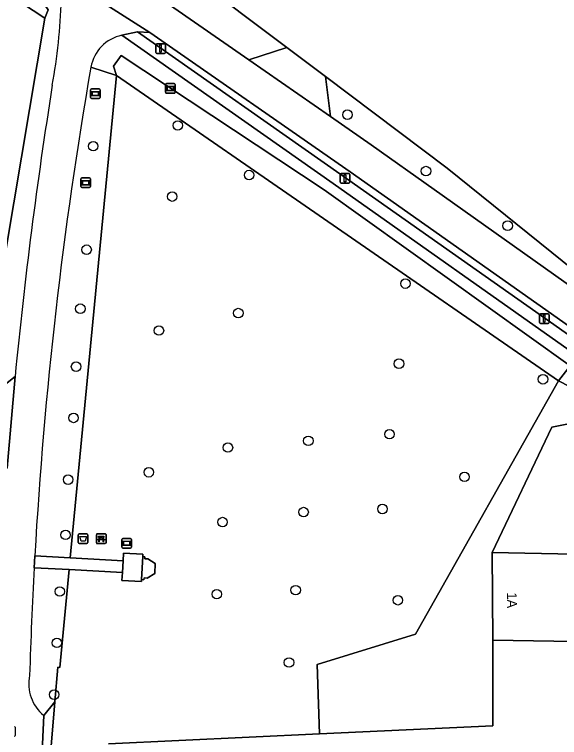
# Model space of a CAD drawing. Extents: x 163859 to 164644, y 379566 to 382155.
# Drawn here: x 164442.4 to 164498.5, y 381606.4 to 381680.8 of the extents above; entities that cross this region are included whole.
import ezdxf

# ---------------------------------------------------------------- set-up
doc = ezdxf.new("R2010")
doc.units = 0
for name, color, linetype in [('IMGEO_Afvalbak', 7, 'Continuous'), ('IMGEO_Bank', 7, 'Continuous'), ('IMGEO_Boom', 7, 'Continuous'), ('IMGEO_Erf', 7, 'Continuous'), ('IMGEO_Groenvoorziening', 7, 'Continuous'), ('IMGEO_Haag', 7, 'Continuous'), ('IMGEO_Hek', 7, 'Continuous'), ('IMGEO_Informatiebord', 7, 'Continuous'), ('IMGEO_Lichtmast', 7, 'Continuous'), ('IMGEO_Loofbos', 7, 'Continuous'), ('IMGEO_Pand', 7, 'Continuous'), ('IMGEO_Pand_nummerreeks', 7, 'Continuous'), ('IMGEO_Rijbaan_lokaal_gesloten', 7, 'Continuous'), ('IMGEO_Rioolput', 7, 'Continuous'), ('IMGEO_Verklikker', 7, 'Continuous'), ('IMGEO_Voetpad_open', 7, 'Continuous'), ('IMGEO_Waterloop', 7, 'Continuous'), ('IMGEO_Wegwijzer', 7, 'Continuous')]:
    doc.layers.add(name, color=color, linetype=linetype)

msp = doc.modelspace()

# ---------------------------------------------------------------- linework, layer by layer
at = {"layer": 'IMGEO_Afvalbak'}
for p, q in [((164448.954, 381626.452), (164448.954, 381627.252)), ((164448.954, 381627.252), (164448.954, 381626.452)), ((164449.054, 381627.352), (164449.844, 381627.352)), ((164449.844, 381627.352), (164449.054, 381627.352)), ((164449.944, 381627.252), (164449.944, 381626.452)), ((164449.944, 381626.452), (164449.944, 381627.252)), ((164449.844, 381626.352), (164449.054, 381626.352)), ((164449.054, 381626.352), (164449.844, 381626.352))]:
    msp.add_line(p, q, dxfattribs=at)
msp.add_lwpolyline([(164449.097, 381627.066), (164449.801, 381627.066), (164449.652, 381626.596), (164449.246, 381626.596), (164449.097, 381627.066)], dxfattribs=at)
for centre, start, end in [((164449.054, 381627.252), 90, 180), ((164449.054, 381627.252), 90, 180), ((164449.844, 381627.252), 0, 90), ((164449.844, 381627.252), 360, 90), ((164449.054, 381626.452), 180, 270), ((164449.054, 381626.452), 180, 270), ((164449.844, 381626.452), 270, 0), ((164449.844, 381626.452), 270, 0)]:
    msp.add_arc(centre, 0.1, start, end, dxfattribs=at)
at = {"layer": 'IMGEO_Bank'}
for p, q in [((164450.809, 381626.422), (164450.809, 381627.263)), ((164450.809, 381627.263), (164450.809, 381626.422)), ((164450.884, 381627.347), (164451.725, 381627.347)), ((164451.725, 381627.347), (164450.884, 381627.347)), ((164451.118, 381626.853), (164451.118, 381626.959)), ((164451.162, 381626.959), (164451.162, 381626.853)), ((164451.45, 381626.965), (164451.168, 381626.965)), ((164451.168, 381626.847), (164451.45, 381626.847)), ((164451.456, 381626.853), (164451.456, 381626.959)), ((164451.5, 381626.959), (164451.5, 381626.853)), ((164451.809, 381627.272), (164451.809, 381626.431)), ((164451.809, 381626.431), (164451.809, 381627.272)), ((164451.734, 381626.347), (164450.893, 381626.347)), ((164450.893, 381626.347), (164451.734, 381626.347)), ((164451.506, 381626.745), (164451.113, 381626.745))]:
    msp.add_line(p, q, dxfattribs=at)
for points in [[(164451.056, 381626.745), (164450.914, 381626.745), (164451.026, 381626.847), (164451.112, 381626.847)], [(164451.112, 381626.965), (164451.026, 381626.965), (164451.026, 381627.126), (164451.589, 381627.126), (164451.589, 381626.965), (164451.506, 381626.965)], [(164451.506, 381626.847), (164451.589, 381626.847), (164451.701, 381626.745), (164451.562, 381626.745)], [(164451.106, 381626.738), (164451.106, 381626.531), (164451.063, 381626.531), (164451.063, 381626.738)], [(164451.556, 381626.738), (164451.556, 381626.531), (164451.512, 381626.531), (164451.512, 381626.738)]]:
    msp.add_lwpolyline(points, dxfattribs=at)
for centre, radius, start, end in [((164450.887, 381627.269), 0.0779, 92.4484, 184.28452), ((164450.887, 381627.269), 0.0779, 92.4484, 184.28452), ((164451.111, 381626.958), 0.00671, 2.89567, 87.10433), ((164451.111, 381626.854), 0.00671, 272.89567, 357.10433), ((164451.168, 381626.958), 0.00671, 92.89567, 177.10433), ((164451.168, 381626.854), 0.00671, 182.89567, 267.10433), ((164451.45, 381626.958), 0.00671, 2.89567, 87.10433), ((164451.45, 381626.854), 0.00671, 272.89567, 357.10433), ((164451.507, 381626.958), 0.00671, 92.89567, 177.10433), ((164451.507, 381626.854), 0.00671, 182.89567, 267.10433), ((164451.731, 381627.269), 0.0779, 2.4484, 94.28452), ((164451.731, 381627.269), 0.0779, 2.4484, 94.28452), ((164450.887, 381626.425), 0.0779, 182.4484, 274.28452), ((164450.887, 381626.425), 0.0779, 182.4484, 274.28452), ((164451.056, 381626.738), 0.00671, 2.89567, 87.10433), ((164451.113, 381626.738), 0.00671, 92.89567, 177.10433), ((164451.505, 381626.738), 0.00671, 2.89567, 87.10433), ((164451.562, 381626.738), 0.00671, 92.89567, 177.10433), ((164451.731, 381626.425), 0.0779, 272.4484, 4.28452), ((164451.731, 381626.425), 0.0779, 272.4484, 4.28452)]:
    msp.add_arc(centre, radius, start, end, dxfattribs=at)
at = {"layer": 'IMGEO_Boom'}
for centre in [(164476.665, 381670.499), (164459.197, 381669.393), (164450.485, 381667.25), (164466.538, 381664.286), (164484.752, 381664.694), (164458.621, 381662.067), (164493.161, 381659.073), (164449.805, 381656.599), (164482.639, 381653.106), (164449.161, 381650.525), (164465.427, 381650.075), (164457.255, 381648.275), (164448.719, 381644.56), (164481.97, 381644.867), (164496.797, 381643.258), (164448.464, 381639.282), (164480.993, 381637.606), (164472.636, 381636.923), (164464.36, 381636.23), (164456.212, 381633.684), (164488.717, 381633.215), (164447.903, 381632.926), (164472.149, 381629.589), (164480.27, 381629.907), (164463.805, 381628.56), (164447.636, 381627.239), (164447.045, 381621.415), (164463.212, 381621.138), (164471.332, 381621.555), (164481.856, 381620.51), (164446.75, 381616.126), (164470.647, 381614.104), (164446.459, 381610.795)]:
    msp.add_circle(centre, 0.489, dxfattribs=at)
at = {"layer": 'IMGEO_Erf'}
for points in [[(164460.508, 381684.892), (164470.413, 381677.426), (164474.397, 381674.423), (164486.922, 381664.983), (164500, 381654.462), (164509.162, 381647.672), (164516.979, 381640.96), (164517.33, 381641.342), (164526.033, 381633.218), (164529.147, 381634.828), (164538.792, 381645.898), (164541.993, 381649.77), (164537.255, 381661.598), (164540.318, 381662.825), (164543.407, 381655.115), (164544.635, 381652.966), (164545.262, 381652.467), (164553.793, 381662.786), (164565.496, 381676.942), (164583.03, 381701.542)], [(164504.238, 381639.639), (164497.717, 381638.341), (164491.561, 381625.418), (164500, 381625.257), (164511.742, 381625.032), (164511.845, 381616.048), (164500, 381616.257), (164491.641, 381616.405), (164491.641, 381607.592), (164473.792, 381606.759), (164452.065, 381605.746)]]:
    msp.add_lwpolyline(points, dxfattribs=at)
at = {"layer": 'IMGEO_Groenvoorziening'}
for points in [[(164455.903, 381683.819), (164455.774, 381683.629), (164466.526, 381676.141), (164470.413, 381677.426), (164460.508, 381684.892), (164456.242, 381696.233), (164452.839, 381705.104), (164451.098, 381709.418), (164447.311, 381716.527), (164449.308, 381717.487), (164446.861, 381722.173), (164445.218, 381721.442), (164440.48, 381732.584), (164442.117, 381733.052), (164440.833, 381734.263), (164434.331, 381751.745), (164433.997, 381752.734), (164433.526, 381754.803), (164427.546, 381772.442), (164427.349, 381773.022), (164418.253, 381799.855)], [(164413.488, 381705.549), (164411.502, 381706.899), (164410.178, 381704.987), (164411.398, 381704.132), (164412.893, 381702.27), (164413.634, 381703.357), (164430.229, 381692.16), (164429.462, 381691.018), (164430.172, 381690.536), (164431.154, 381689.854), (164431.926, 381691.02), (164445.149, 381682.312), (164445.862, 381681.301), (164445.507, 381680.437), (164441.513, 381656.721), (164439.427, 381648.452), (164432.979, 381644.03), (164435.396, 381638.772), (164437.55, 381639.663), (164442.442, 381643.541)], [(164501.109, 381647.553), (164500, 381648.336), (164476.958, 381664.61), (164456.317, 381678.951), (164455.059, 381679.039), (164475.88, 381664.403), (164500, 381647.421), (164500.789, 381646.866)], [(164500.075, 381645.858), (164475.205, 381663.4), (164453.434, 381678.671)], [(164450.243, 381675.391), (164452.879, 381674.516), (164452.567, 381675.49), (164453.363, 381676.591), (164474.271, 381662.773), (164499.591, 381644.652), (164498.403, 381643.097), (164501.803, 381641.347), (164502.858, 381642.512)], [(164444.471, 381625.076), (164448.124, 381624.873), (164452.879, 381674.516), (164450.243, 381675.391)], [(164498.403, 381643.097), (164452.879, 381674.516), (164448.124, 381624.873), (164453.557, 381624.572), (164453.606, 381625.363), (164455.592, 381625.266), (164455.587, 381625.002), (164455.795, 381624.993), (164455.786, 381624.774), (164456.113, 381624.78), (164456.861, 381624.28), (164456.823, 381623.267), (164456.038, 381622.8), (164455.723, 381622.822), (164455.709, 381622.622), (164455.463, 381622.639), (164455.452, 381622.46), (164453.447, 381622.561), (164453.504, 381623.384), (164448.008, 381623.666), (164447.044, 381613.598), (164446.845, 381613.615), (164446.54, 381610.042), (164445.729, 381600.527)], [(164500, 381654.462), (164486.922, 381664.983), (164474.397, 381674.423), (164474.908, 381670.303), (164479.098, 381667.385), (164485.583, 381662.794), (164500, 381652.587), (164503.048, 381650.429)], [(164452.065, 381605.746), (164473.792, 381606.759), (164473.688, 381609.802), (164473.548, 381613.906), (164483.66, 381617.038), (164498.403, 381643.097)], [(164446.039, 381571.665), (164445.919, 381582.439), (164445.846, 381586.661), (164445.965, 381592.66), (164445.764, 381596.44), (164445.787, 381598.852), (164445.729, 381600.527), (164446.54, 381610.042), (164445.386, 381608.654), (164445.211, 381604.21)]]:
    msp.add_lwpolyline(points, dxfattribs=at)
msp.add_lwpolyline([(164445.507, 381680.437), (164431.154, 381689.854), (164430.172, 381690.536), (164418.395, 381675.757), (164432.979, 381644.03), (164439.427, 381648.452), (164441.513, 381656.721)], close=True, dxfattribs=at)
for centre, radius, start, end in [((164384.013, 381684.587), 63.236, 349.92525, 357.95994), ((164454.269, 381674.666), 4.091, 101.77804, 169.79792), ((164886.517, 381599.854), 442.765, 170.17716, 176.73442), ((164930.61, 381596.389), 490.439, 170.95102, 174.48297)]:
    msp.add_arc(centre, radius, start, end, dxfattribs=at)
at = {"layer": 'IMGEO_Haag'}
msp.add_lwpolyline([(164501.109, 381647.553), (164500, 381648.336), (164476.958, 381664.61), (164456.317, 381678.951), (164455.059, 381679.039), (164475.88, 381664.403), (164500, 381647.421), (164500.789, 381646.866)], dxfattribs=at)
at = {"layer": 'IMGEO_Hek'}
msp.add_lwpolyline([(164445.507, 381680.437), (164441.513, 381656.721), (164439.427, 381648.452), (164432.979, 381644.03)], dxfattribs=at)
at = {"layer": 'IMGEO_Informatiebord'}
for p, q in [((164453.544, 381626.877), (164454.334, 381626.877)), ((164454.334, 381626.877), (164453.544, 381626.877)), ((164453.444, 381625.977), (164453.444, 381626.777)), ((164453.444, 381626.777), (164453.444, 381625.977)), ((164454.434, 381626.777), (164454.434, 381625.977)), ((164454.434, 381625.977), (164454.434, 381626.777)), ((164454.334, 381625.877), (164453.544, 381625.877)), ((164453.544, 381625.877), (164454.334, 381625.877))]:
    msp.add_line(p, q, dxfattribs=at)
for points in [[(164453.545, 381626.609), (164454.333, 381626.609), (164454.333, 381626.145), (164453.545, 381626.145), (164453.545, 381626.609)], [(164453.61, 381626.544), (164453.61, 381626.21), (164454.268, 381626.21), (164454.268, 381626.544), (164453.61, 381626.544)]]:
    msp.add_lwpolyline(points, dxfattribs=at)
for centre, start, end in [((164453.544, 381626.777), 90, 180), ((164453.544, 381626.777), 90, 180), ((164454.334, 381626.777), 0, 90), ((164454.334, 381626.777), 360, 90), ((164453.544, 381625.977), 180, 270), ((164453.544, 381625.977), 180, 270), ((164454.334, 381625.977), 270, 0), ((164454.334, 381625.977), 270, 0)]:
    msp.add_arc(centre, 0.1, start, end, dxfattribs=at)
at = {"layer": 'IMGEO_Lichtmast'}
for p, q in [((164456.927, 381676.897), (164456.927, 381677.697)), ((164456.927, 381677.697), (164456.927, 381676.897)), ((164457.027, 381677.797), (164457.817, 381677.797)), ((164457.817, 381677.797), (164457.027, 381677.797)), ((164457.917, 381677.697), (164457.917, 381676.897)), ((164457.917, 381676.897), (164457.917, 381677.697)), ((164457.817, 381676.797), (164457.027, 381676.797)), ((164457.027, 381676.797), (164457.817, 381676.797)), ((164475.915, 381663.546), (164475.915, 381664.346)), ((164475.915, 381664.346), (164475.915, 381663.546)), ((164476.015, 381664.446), (164476.805, 381664.446)), ((164476.805, 381664.446), (164476.015, 381664.446)), ((164476.905, 381664.346), (164476.905, 381663.546)), ((164476.905, 381663.546), (164476.905, 381664.346)), ((164476.805, 381663.446), (164476.015, 381663.446)), ((164476.015, 381663.446), (164476.805, 381663.446)), ((164496.432, 381649.104), (164496.432, 381649.904)), ((164496.432, 381649.904), (164496.432, 381649.104)), ((164496.532, 381650.004), (164497.322, 381650.004)), ((164497.322, 381650.004), (164496.532, 381650.004)), ((164497.422, 381649.904), (164497.422, 381649.104)), ((164497.422, 381649.104), (164497.422, 381649.904)), ((164497.322, 381649.004), (164496.532, 381649.004)), ((164496.532, 381649.004), (164497.322, 381649.004))]:
    msp.add_line(p, q, dxfattribs=at)
for points in [[(164457.347, 381677.672), (164457.497, 381677.672), (164457.497, 381676.922), (164457.347, 381676.922), (164457.347, 381677.672)], [(164476.335, 381664.321), (164476.485, 381664.321), (164476.485, 381663.571), (164476.335, 381663.571), (164476.335, 381664.321)], [(164496.852, 381649.879), (164497.002, 381649.879), (164497.002, 381649.129), (164496.852, 381649.129), (164496.852, 381649.879)]]:
    msp.add_lwpolyline(points, dxfattribs=at)
for centre, start, end in [((164457.027, 381677.697), 90, 180), ((164457.027, 381677.697), 90, 180), ((164457.817, 381677.697), 0, 90), ((164457.817, 381677.697), 360, 90), ((164457.027, 381676.897), 180, 270), ((164457.027, 381676.897), 180, 270), ((164457.817, 381676.897), 270, 0), ((164457.817, 381676.897), 270, 0), ((164476.015, 381664.346), 90, 180), ((164476.015, 381664.346), 90, 180), ((164476.805, 381664.346), 0, 90), ((164476.805, 381664.346), 360, 90), ((164476.015, 381663.546), 180, 270), ((164476.015, 381663.546), 180, 270), ((164476.805, 381663.546), 270, 0), ((164476.805, 381663.546), 270, 0), ((164496.532, 381649.904), 90, 180), ((164496.532, 381649.904), 90, 180), ((164497.322, 381649.904), 0, 90), ((164497.322, 381649.904), 360, 90), ((164496.532, 381649.104), 180, 270), ((164496.532, 381649.104), 180, 270), ((164497.322, 381649.104), 270, 0), ((164497.322, 381649.104), 270, 0)]:
    msp.add_arc(centre, 0.1, start, end, dxfattribs=at)
at = {"layer": 'IMGEO_Loofbos'}
for points in [[(164501.803, 381641.347), (164498.403, 381643.097), (164483.66, 381617.038), (164473.548, 381613.906), (164473.688, 381609.802), (164473.792, 381606.759), (164491.641, 381607.592), (164491.641, 381616.405), (164491.561, 381625.418), (164497.717, 381638.341), (164504.238, 381639.639)], [(164445.386, 381608.654), (164446.54, 381610.042), (164446.845, 381613.615), (164447.044, 381613.598), (164448.008, 381623.666), (164444.402, 381623.851)]]:
    msp.add_lwpolyline(points, dxfattribs=at)
for centre, radius, start, end in [((164883.319, 381600.007), 439.564, 176.89047, 178.33678), ((164448.063, 381611.906), 4.212, 168.22638, 230.53116)]:
    msp.add_arc(centre, radius, start, end, dxfattribs=at)
at = {"layer": 'IMGEO_Pand'}
for points in [[(164511.742, 381625.032), (164500, 381625.257), (164491.561, 381625.418), (164491.641, 381616.405), (164500, 381616.257), (164511.845, 381616.048)], [(164455.463, 381622.639), (164455.709, 381622.622), (164455.723, 381622.822), (164456.038, 381622.8), (164456.823, 381623.267), (164456.861, 381624.28), (164456.113, 381624.78), (164455.786, 381624.774), (164455.795, 381624.993), (164455.587, 381625.002)]]:
    msp.add_lwpolyline(points, close=True, dxfattribs=at)
at = {"layer": 'IMGEO_Rijbaan_lokaal_gesloten'}
for points in [[(164503.048, 381650.429), (164500, 381652.587), (164485.583, 381662.794), (164479.098, 381667.385), (164474.908, 381670.303), (164466.526, 381676.141), (164455.774, 381683.629), (164441.191, 381693.787), (164424.684, 381705.234)], [(164424.306, 381700.566), (164445.106, 381686.132), (164456.317, 381678.951), (164476.958, 381664.61), (164500, 381648.336), (164501.109, 381647.553)], [(164453.434, 381678.671), (164455.059, 381679.039), (164456.317, 381678.951), (164445.106, 381686.132), (164446.689, 381684.251), (164446.953, 381683.86)], [(164442.442, 381643.541), (164441.623, 381634.125)], [(164444.402, 381623.851), (164444.436, 381624.464), (164444.471, 381625.076)], [(164445.211, 381604.21), (164445.386, 381608.654)]]:
    msp.add_lwpolyline(points, dxfattribs=at)
for centre, radius, start, end in [((164384.013, 381684.587), 63.236, 349.92525, 357.95994), ((164454.269, 381674.666), 4.091, 101.77804, 169.79792), ((164886.517, 381599.854), 442.765, 170.17716, 176.73442), ((164930.61, 381596.389), 490.439, 170.95102, 174.48297), ((164883.319, 381600.007), 439.564, 176.89047, 178.33678), ((164448.063, 381611.906), 4.212, 168.22638, 230.53116)]:
    msp.add_arc(centre, radius, start, end, dxfattribs=at)
at = {"layer": 'IMGEO_Rioolput'}
msp.add_line((164442.451, 381607.432), (164442.451, 381606.58), dxfattribs=at)
msp.add_lwpolyline([(164442.451, 381607.432), (164442.451, 381606.58)], dxfattribs=at)
for centre, start, end in [((164442.375, 381607.43), 1.55205, 88.44795), ((164442.375, 381607.43), 1.55205, 88.44795), ((164442.375, 381606.582), 271.55205, 358.44795), ((164442.375, 381606.582), 271.55205, 358.44795)]:
    msp.add_arc(centre, 0.0765, start, end, dxfattribs=at)
at = {"layer": 'IMGEO_Verklikker'}
for p, q in [((164458.043, 381673.701), (164458.833, 381673.701)), ((164458.833, 381673.701), (164458.043, 381673.701)), ((164457.943, 381672.801), (164457.943, 381673.601)), ((164457.943, 381673.601), (164457.943, 381672.801)), ((164458.933, 381673.601), (164458.933, 381672.801)), ((164458.933, 381672.801), (164458.933, 381673.601)), ((164458.833, 381672.701), (164458.043, 381672.701)), ((164458.043, 381672.701), (164458.833, 381672.701))]:
    msp.add_line(p, q, dxfattribs=at)
for points in [[(164458.044, 381673.433), (164458.832, 381673.433), (164458.832, 381672.969), (164458.044, 381672.969), (164458.044, 381673.433)], [(164458.109, 381673.368), (164458.109, 381673.034), (164458.767, 381673.034), (164458.767, 381673.368), (164458.109, 381673.368)]]:
    msp.add_lwpolyline(points, dxfattribs=at)
for centre, start, end in [((164458.043, 381673.601), 90, 180), ((164458.043, 381673.601), 90, 180), ((164458.833, 381673.601), 0, 90), ((164458.833, 381673.601), 360, 90), ((164458.043, 381672.801), 180, 270), ((164458.043, 381672.801), 180, 270), ((164458.833, 381672.801), 270, 0), ((164458.833, 381672.801), 270, 0)]:
    msp.add_arc(centre, 0.1, start, end, dxfattribs=at)
at = {"layer": 'IMGEO_Voetpad_open'}
msp.add_lwpolyline([(164500.789, 381646.866), (164500, 381647.421), (164475.88, 381664.403), (164455.059, 381679.039), (164453.434, 381678.671), (164475.205, 381663.4), (164500.075, 381645.858)], dxfattribs=at)
for points in [[(164470.413, 381677.426), (164466.526, 381676.141), (164474.908, 381670.303), (164474.397, 381674.423)], [(164435.396, 381638.772), (164437.24, 381634.76), (164441.623, 381634.125), (164442.442, 381643.541), (164437.55, 381639.663)], [(164453.504, 381623.384), (164453.447, 381622.561), (164455.452, 381622.46), (164455.463, 381622.639), (164455.587, 381625.002), (164455.592, 381625.266), (164453.606, 381625.363), (164453.557, 381624.572)], [(164444.402, 381623.851), (164448.008, 381623.666), (164453.504, 381623.384), (164453.557, 381624.572), (164448.124, 381624.873), (164444.471, 381625.076), (164444.436, 381624.464)]]:
    msp.add_lwpolyline(points, close=True, dxfattribs=at)
at = {"layer": 'IMGEO_Waterloop'}
for points in [[(164445.862, 381681.301), (164445.149, 381682.312), (164431.926, 381691.02), (164431.154, 381689.854), (164445.507, 381680.437)], [(164498.403, 381643.097), (164499.591, 381644.652), (164474.271, 381662.773), (164453.363, 381676.591), (164452.567, 381675.49), (164452.879, 381674.516)]]:
    msp.add_lwpolyline(points, close=True, dxfattribs=at)
at = {"layer": 'IMGEO_Wegwijzer'}
for p, q in [((164450.198, 381672.266), (164450.198, 381673.066)), ((164450.198, 381673.066), (164450.198, 381672.266)), ((164450.298, 381673.166), (164451.088, 381673.166)), ((164451.088, 381673.166), (164450.298, 381673.166)), ((164451.188, 381673.066), (164451.188, 381672.266)), ((164451.188, 381672.266), (164451.188, 381673.066)), ((164451.088, 381672.166), (164450.298, 381672.166)), ((164450.298, 381672.166), (164451.088, 381672.166)), ((164449.206, 381663.091), (164449.206, 381663.891)), ((164449.206, 381663.891), (164449.206, 381663.091)), ((164449.306, 381663.991), (164450.096, 381663.991)), ((164450.096, 381663.991), (164449.306, 381663.991)), ((164450.196, 381663.891), (164450.196, 381663.091)), ((164450.196, 381663.091), (164450.196, 381663.891)), ((164450.096, 381662.991), (164449.306, 381662.991)), ((164449.306, 381662.991), (164450.096, 381662.991))]:
    msp.add_line(p, q, dxfattribs=at)
for points in [[(164450.299, 381672.898), (164451.087, 381672.898), (164451.087, 381672.434), (164450.299, 381672.434), (164450.299, 381672.898)], [(164450.364, 381672.833), (164450.364, 381672.499), (164451.022, 381672.499), (164451.022, 381672.833), (164450.364, 381672.833)], [(164449.307, 381663.723), (164450.095, 381663.723), (164450.095, 381663.259), (164449.307, 381663.259), (164449.307, 381663.723)], [(164449.372, 381663.658), (164449.372, 381663.324), (164450.03, 381663.324), (164450.03, 381663.658), (164449.372, 381663.658)]]:
    msp.add_lwpolyline(points, dxfattribs=at)
for centre, start, end in [((164450.298, 381673.066), 90, 180), ((164450.298, 381673.066), 90, 180), ((164451.088, 381673.066), 0, 90), ((164451.088, 381673.066), 360, 90), ((164450.298, 381672.266), 180, 270), ((164450.298, 381672.266), 180, 270), ((164451.088, 381672.266), 270, 0), ((164451.088, 381672.266), 270, 0), ((164449.306, 381663.891), 90, 180), ((164449.306, 381663.891), 90, 180), ((164450.096, 381663.891), 0, 90), ((164450.096, 381663.891), 360, 90), ((164449.306, 381663.091), 180, 270), ((164449.306, 381663.091), 180, 270), ((164450.096, 381663.091), 270, 0), ((164450.096, 381663.091), 270, 0)]:
    msp.add_arc(centre, 0.1, start, end, dxfattribs=at)

# ---------------------------------------------------------------- texts
at = {"layer": 'IMGEO_Pand_nummerreeks'}
msp.add_text('1A', height=1, rotation=270.30919, dxfattribs=at).set_placement((164493.101, 381621.331))

doc.saveas('drawing.dxf')
